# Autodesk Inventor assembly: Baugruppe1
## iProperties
Shininess: 64.0
Length Units: 11269
Angle Units: 11279
Time Units: 11290
Mass Units: 11283
Length Display Precision: 3
Angle Display Precision: 2
Compacted: True
Created: 2006-04
Part Number: Baugruppe1
Document SubType Name: Assembly
Designer: IQ-Man
Manufacturer: Standard
Standards Organization: Custom
Density: 0.0
Volumn: 0.0
Area: 0.0
PropertySet Name: Model Information
Control State: 0
Master: False
Checked Out: False
Author: IQ-Man
